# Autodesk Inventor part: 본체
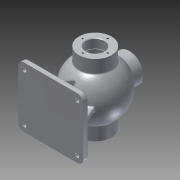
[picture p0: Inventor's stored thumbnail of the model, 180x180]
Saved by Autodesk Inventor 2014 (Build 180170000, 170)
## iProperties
Created: 2017-01
Part Number: 본체
Material: Aluminum 6061
Document SubType Name: Modeling
Designer: ksu
Density: 2.71 g/cm^3
Appearance: Aluminum - Flat
Mass: 1509.55 g
Surface Area: 1153.31 cm^2
Volume: 557.028 cm^3
Author: ksu
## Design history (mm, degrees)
sketch "Sketch1"
  geometry: L1 (0, -53)-(0, 53); A1 r 53 centre (0, 0) between (0, -53) and (0, 53); 1 further point
  constraints: 2 end point, 2 point on circle, 1 centre point, 1 coincident, 1 vertical
  dimensions: "d0" = 106 diameter of A1
revolve "Revolution1" sketch "Sketch1" stored, may be unused: angle "d1" = 90 deg
node "Sketch2"
workplane "Work Plane1"
sketch "Sketch3"
  geometry: C1 r 31 at (0, 0); 1 further point
  constraints: 1 centre point, 1 coincident
  dimensions: "d6" = 62 diameter of C1
extrude "Extrusion1" join sketch "Sketch3" distance "d7" = 27.4625; taper "d8" = 0 deg
node "Sketch4"
mirror "Mirror1"
sketch "Sketch5"
  geometry: C1 r 31 at (0, 0) reference; C2 r 17.5 at (0, 0)
  constraints: 1 centre point, 1 coincident
  dimensions: "d10" = 35 diameter of C2
extrude "Extrusion2" cut sketch "Sketch5" stored distance "d11" = 27.4625; taper "d12" = 0 deg
chamfer "Chamfer1" distance "d13" = 1; stored, may be unused: second distance "d14" = 2, angle "d15" = 45 deg
sketch "Sketch6"
  geometry: L1 (0, -43)-(0, 43); A1 r 43 centre (0, 0) between (0, -43) and (0, 43); 1 further point
  constraints: 2 end point, 2 point on circle, 1 centre point, 1 coincident, 1 vertical
  dimensions: "d16" = 86 diameter of A1
revolve "Revolution2" sketch "Sketch6" stored, may be unused: angle "d17" = 90 deg
sketch "Sketch7"
  geometry: L1 (52, -18.5)-(52, 0); L2 (50.25, -18.5)-(50.25, 0); L3 (50.25, -18.5)-(52, -18.5); L4 (50.25, 0)-(52, 0); 1 further point
  constraints: 8 end point, 2 parallel, 1 perpendicular
  dimensions: "d19" = 1.75 distance between parallel lines of L2 L1
revolve "Revolution3" sketch "Sketch7" stored, may be unused: angle "d21" = 90 deg
sketch "Sketch8"
  geometry: 4 further points
hole "Hole1" sketch "Sketch8" at (0, 22.5), (22.5, 0), (0, -22.5), (-22.5, 0) diameter "d23" = 3.242; stored, may be unused: countersink angle "d27" = 90 deg, drill point angle "d29" = 118 deg; dims "d24" = 12, "d25" = 4, "d26" = 2, "d28" = 15
sketch "Sketch9"
  geometry: 4 further points
hole "Hole2" sketch "Sketch9" at (0, 24), (24, 0), (-24, 0), (0, -24) diameter "d31" = 3.242; stored, may be unused: countersink angle "d35" = 90 deg, drill point angle "d37" = 118 deg; dims "d32" = 16, "d33" = 4, "d34" = 2, "d36" = 19
workplane "Work Plane2"
sketch "Sketch10"
  geometry: L1 (62.5, -57.5)-(-62.5, -57.5); L2 (-62.5, -57.5)-(-62.5, 57.5); L3 (-62.5, 57.5)-(62.5, 57.5); L4 (62.5, 57.5)-(62.5, -57.5); L5 (62.5, -57.5)-(-62.5, 57.5); L6 (-62.5, -57.5)-(62.5, 57.5); 1 further point
  constraints: 12 end point, 2 midpoint, 2 parallel, 1 horizontal, 1 perpendicular
  dimensions: "d83" = 125 distance of L2.end L3.end; "d84" = 115 distance of L1.end L2.end
extrude "Extrusion3" join sketch "Sketch10" distance "d44" = 10; taper "d45" = 0 deg
workplane "Work Plane3"
sketch "Sketch11"
  geometry: C1 r 27 at (0, 0); 1 further point
  constraints: 1 centre point, 1 coincident
  dimensions: "d48" = 54 diameter of C1
extrude "Extrusion4" join sketch "Sketch11" distance "d49" = 21.1125; taper "d50" = 0 deg
sketch "Sketch13"
  geometry: C1 r 27 at (0, 0) reference; C2 r 13 at (0, 0)
  constraints: 1 centre point, 1 coincident
  dimensions: "d51" = 26 diameter of C2
extrude "Extrusion5" cut sketch "Sketch13" distance "d52" = 36.9875; taper "d53" = 0 deg
sketch "Sketch14"
  geometry: 4 further points
hole "Hole3" sketch "Sketch14" at (0, 20), (20, 0), (0, -20), (-20, 0) diameter "d55" = 3.242; stored, may be unused: countersink angle "d59" = 90 deg, drill point angle "d61" = 118 deg; dims "d56" = 9, "d57" = 4, "d58" = 2, "d60" = 11
sketch "Sketch15"
  geometry: L1 (49.52, 80)-(31.635, 35.734); L2 (-49.52, 80)-(-31.635, 35.734); L3 (49.52, 80)-(-49.52, 80); A1 r 47.725 centre (0, 0) between (31.635, 35.734) and (-31.635, 35.734)
  constraints: 6 end point, 2 point on circle, 1 centre point
extrude "Extrusion6" join sketch "Sketch15" stored distance "d64" = 8; taper "d65" = 0 deg
sketch "Sketch16"
  geometry: L1 (-54.52, 80)-(-35.476, 32.865); L2 (54.52, 80)-(35.476, 32.865); L3 (-54.52, 80)-(54.52, 80); A1 r 48.36 centre (0, 0) between (35.476, 32.865) and (-35.476, 32.865)
  constraints: 6 end point, 2 point on circle, 1 centre point
extrude "Extrusion7" join sketch "Sketch16" stored distance "d68" = 8; taper "d69" = 0 deg
sketch "Sketch17"
  geometry: C1 r 6 at (-50.5, 45.5); C2 r 6 at (50.5, 45.5); C3 r 6 at (-50.5, -45.5); C4 r 6 at (50.5, -45.5)
  constraints: 4 centre point
  dimensions: "d89" = 12 diameter of C1
extrude "Extrusion8" cut sketch "Sketch17" distance "d73" = 3; taper "d74" = 0 deg
fillet "Fillet2" dims "d78" = 3
fillet "Fillet4" dims "d80" = 3
fillet "Fillet5" dims "d81" = 3
fillet "Fillet6" dims "d85" = 12
sketch "Sketch19"
  geometry: C1 r 6 at (0, 0) reference; C2 r 4 at (0, 0); 1 further point
  constraints: 1 centre point, 1 coincident
  dimensions: "d95" = 8 diameter of C2
extrude "Extrusion10" cut sketch "Sketch19" distance "d96" = 10; taper "d97" = 0 deg
mirror "Mirror5"
mirror "Mirror6"
fillet "Fillet7" dims "d98" = 3
fillet "Fillet8" dims "d101" = 3
fillet "Fillet9" dims "d102" = 3
fillet "Fillet10" dims "d103" = 3
fillet "Fillet11" dims "d106" = 3
fillet "Fillet12" dims "d107" = 3
body "Solid1"
other parameters: "d5" = 68, "d20" = 18.5, "d38" = 85
